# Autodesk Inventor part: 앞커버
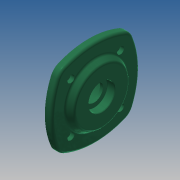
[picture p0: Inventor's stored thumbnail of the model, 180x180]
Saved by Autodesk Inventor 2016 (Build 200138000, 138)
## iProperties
Created: 2015-11
Part Number: 앞커버
Material: 알루미늄 6061
Document SubType Name: Modeling
Designer: mduedu
Density: 2.71 g/cm^3
Appearance: 매끄러움 - 짙은 바다 녹색
Mass: 305.843 g
Surface Area: 251.176 cm^2
Volume: 112.857 cm^3
Author: mduedu
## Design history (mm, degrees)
sketch "스케치1"
  geometry: L1 (50, 50)-(-50, 50); L2 (-50, 50)-(-50, -50); L3 (-50, -50)-(50, -50); L4 (50, -50)-(50, 50); L5 (0, 50)-(0, -50); L6 (50, 0)-(-50, 0); A1 r 90 centre (-40, 0) between (40.415, -40.415) and (40.415, 40.415); A2 r 90 centre (40, 0) between (-40.415, 40.415) and (-40.415, -40.415); A3 r 90 centre (0, -40) between (40.415, 40.415) and (-40.415, 40.415); A4 r 90 centre (0, 40) between (-40.415, -40.415) and (40.415, -40.415); 2 further points
  constraints: 12 end point, 8 point on circle, 5 midpoint, 4 centre point, 2 horizontal alignment, 2 parallel, 2 perpendicular, 2 symmetric about line, 2 tangent, 2 vertical alignment, 1 equal radius, 1 horizontal, 2 other
  dimensions: "d0" = 100 distance of L3.end L1.start; "d2" = 90 radius of A1
extrude "돌출1" new body sketch "스케치1" distance "d3" = 8; taper "d4" = 0 deg
sketch "스케치2"
  geometry: C1 r 35 at (0, 0); 1 further point
  constraints: 1 centre point, 1 coincident
  dimensions: "d5" = 70 diameter of C1
extrude "돌출2" join sketch "스케치2" distance "d6" = 7; taper "d7" = -30 deg
sketch "스케치3"
  geometry: L1 (0, 0)-(0, 40); L2 (0, 0)-(-28.284, 28.284); A1 r 40 centre (0, 0) between (0, 40) and (-28.284, 28.284); 2 further points
  constraints: 4 end point, 2 coincident, 2 point on circle, 1 centre point, 1 vertical
  dimensions: "d8" = 80 diameter of A1; "d9" = 45 deg angle of L1 L2
hole "구멍1" sketch "스케치3" at (-28.284, 28.284) diameter "d11" = 4.5; stored, may be unused: countersink angle "d15" = 90 deg, drill point angle "d17" = 118 deg; dims "d12" = 6, "d13" = 8, "d14" = 4.4, "d16" = 8
sketch "스케치4"
  geometry: C1 r 35 at (0, 0); 1 further point
  constraints: 1 centre point, 1 coincident
  dimensions: "d21" = 70 diameter of C1
extrude "돌출3" join sketch "스케치4" distance "d23" = 12; taper "d24" = 0 deg
hole "구멍2" diameter "d27" = 30; stored, may be unused: countersink angle "d31" = 90 deg, drill point angle "d33" = 0 deg; dims "d25" = 10, "d26" = 10, "d28" = 6, "d29" = 40, "d30" = 12, "d32" = 15
fillet "모깎기2" dims "d35" = 15
fillet "모깎기3" dims "d36" = 3
fillet "모깎기4" dims "d37" = 3
fillet "모깎기5" dims "d38" = 0.3
chamfer "모따기1" distance "d39" = 1; stored, may be unused: second distance "d40" = 2, angle "d41" = 45 deg
hole "구멍3" diameter "d44" = 20; stored, may be unused: countersink angle "d48" = 90 deg, drill point angle "d50" = 118 deg; dims "d45" = 6, "d46" = 30, "d47" = 8.7, "d49" = 8, "d55" = 10, "d56" = 10
fillet "모깎기6" dims "d51" = 0.3
chamfer "모따기2" distance "d52" = 0.7; stored, may be unused: second distance "d53" = 2, angle "d54" = 30 deg
node "솔리드1"
pattern_circular "원형 패턴1" dims angle "d19" = 360 deg
